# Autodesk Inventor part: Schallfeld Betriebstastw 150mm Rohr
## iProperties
Shininess: 20.0
Length Units: 11269
Angle Units: 11279
Time Units: 11290
Mass Units: 11283
Length Display Precision: 2
Angle Display Precision: 2
Part Number: Schallfeld Betriebstastw 150mm Rohr
Material: Lexan (klar)
Document SubType Name: Modellieren
Description: Schallfeld 0,15m
Checked By: Alves
Created: 2004-12
Designer: Ohle
Manufacturer: Standard
Standards Organization: Custom
Density: 0.0
Volumn: 0.0
Area: 0.0
PropertySet Name: Model Information
Control State: 0
Master: False
Checked Out: False
Last Check In By: ohle
Last Check In Date: 2005-08-23
ME: ST
Title: Schallfelder
Author: Ohle
Comments: keine Bemerkung
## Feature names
1. Innenglocke [Revolution]
